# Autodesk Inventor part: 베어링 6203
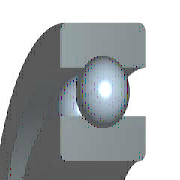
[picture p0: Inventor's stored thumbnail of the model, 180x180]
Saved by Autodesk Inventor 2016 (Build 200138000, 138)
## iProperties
Created: 2012-02
Part Number: 베어링 6203
Material: 강철, 연강
Description: 깊은 그루브 볼 베어링
Document SubType Name: Modeling
Standard: KS B 2023
Designer: mduedu
Standards Organization: KS
Language: ko-KR
Size Designation: 6203 - 17 x 40 x 12
Categories: <MemberInstance><Categories><Category DisplayName="샤프트 부품" InternalName="7f7aeb1f-a693-4053-b835-cee3144e0d98" Mnemonic="SHFT"><Category DisplayName="베어링" Inter
Density: 7.85 g/cm^3
Appearance: 노란색
Mass: 64.8982 g
Surface Area: 64.3582 cm^2
Volume: 8.26729 cm^3
IsCustomPart: 1
Author: mduedu
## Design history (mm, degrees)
sketch "스케치" dims "d0" = 5.98 (= -0.26 x WD + 0.26 x BD)
  geometry: L1 (3.01, 14.25)-(8.99, 14.25); L2 (6, 14.25)-(6, 11.26); L3 (6, 14.25)-(6, 17.24); L4 (3.778, 12.249)-(0, 12.249); L5 (0, 8.5)-(12, 8.5); L6 (3.778, 16.251)-(0, 16.251); L7 (0, 20)-(12, 20); L8 (12, 8.5)-(12, 12.249); L9 (8.222, 12.249)-(12, 12.249); L10 (8.222, 16.251)-(12, 16.251); L11 (12, 20)-(12, 16.251); L12 (-1.4, 0)-(8.4, 0) reference; L13 (0, -0.3)-(0, 5.3) reference
  constraints: 22 end point, 4 point on line, 2 collinear, 2 perpendicular, 2 symmetric about line, 1 midpoint, 1 parallel, 14 other
  dimensions: "d9" = 17 diameter of L5 L12 (= WD); "d11" = 40 diameter of L7 L12 (= BD); "d12" = 12 distance between parallel lines of L8 L13 (= KB); "d13" = 24.498 diameter of L9 L12 (= 0.326 x BD + 0.674 x WD)
revolve "본체" stored, may be unused: angle "d6" = 90 deg
revolve "볼" stored, may be unused: angle "d7" = 90 deg
pattern_circular "IDS_ARRAYBALL[SIMPL:T]" dims angle "d3" = 360 deg
body "Solid1"
fillet "모깎기1" dims "d1" = 0.6 (= KRS)
other parameters: "WD" = 17 [user parameter; used in 5 equation terms], "BD" = 40 [user parameter; used in 5 equation terms], "KB" = 12 [user parameter; used in 1 equation term], "KRS" = 0.6 [user parameter; used in 1 equation term], "d4" = 0, "d5" = 0, "d8" = 0, "d14" = 0, "d15" = 0, "BBA" = 0 [user parameter], "BC0" = 4750000 [user parameter], "BC" = 9560000 [user parameter], "WR" = 8.5 (= 0.5 x WD) [user parameter]
